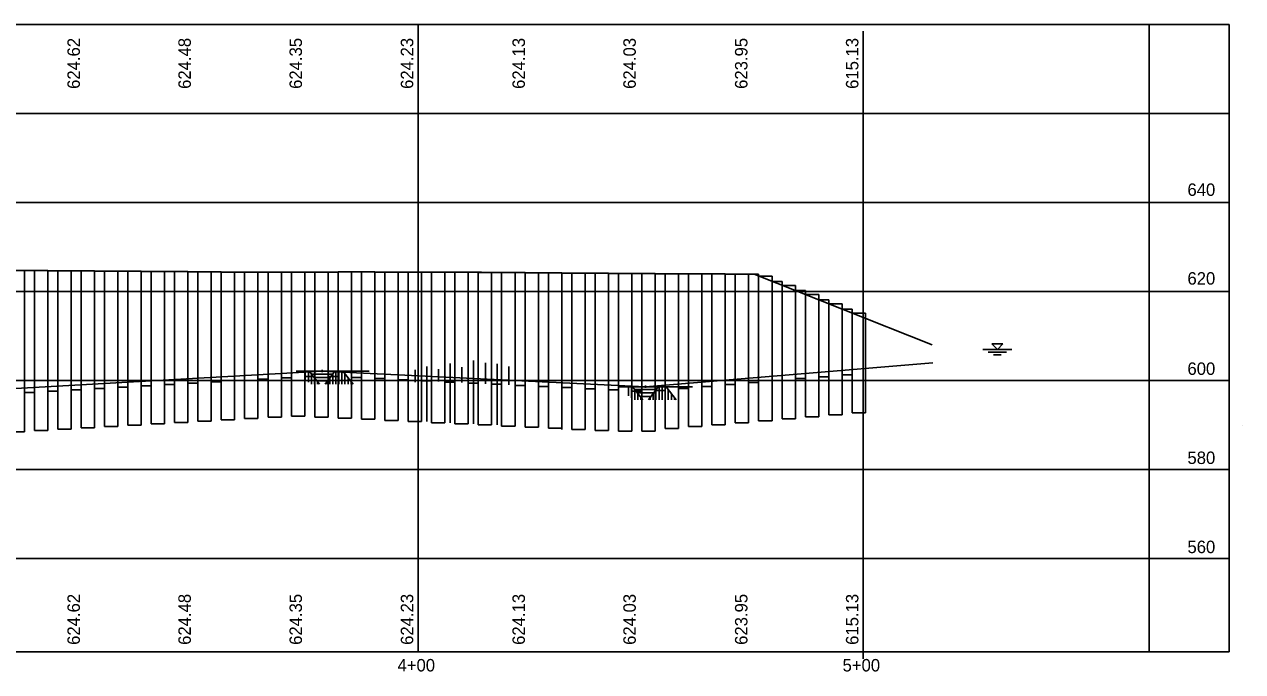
# Model space of a CAD drawing. Extents: x 2267596 to 2268160, y 712626 to 714793.
# Drawn here: x 2267886 to 2268159.8, y 713757.9 to 713903.3 of the extents above; entities that cross this region are included whole.
import ezdxf

# ---------------------------------------------------------------- set-up
doc = ezdxf.new("R2010")
doc.units = 0
for name, color, linetype in [('BR_P_Gen_Text', 7, 'Continuous'), ('BR_P_Sub_Deep_Object', 7, 'Continuous'), ('Default', 7, 'Continuous'), ('GE_X_Alignment', 7, 'Continuous'), ('PF_X_Ground_Line', 7, 'Continuous'), ('SC_Scratch1', 7, 'Continuous'), ('SC_Scratch9', 7, 'Continuous'), ('SH_Major_Grid_Line', 7, 'Continuous'), ('UT_P_Water_Cells', 7, 'Continuous'), ('XS_X_Ground_Line', 7, 'Continuous')]:
    doc.layers.add(name, color=color, linetype=linetype)

msp = doc.modelspace()

# ---------------------------------------------------------------- linework, layer by layer
at = {"layer": 'BR_P_Sub_Deep_Object'}
for p, q in [((2267883.03, 713848.02), (2267886.03, 713848.02)), ((2267886.03, 713848.02), (2267886.03, 713811.8)), ((2267886.03, 713848.01), (2267888.28, 713848.01)), ((2267888.28, 713848), (2267888.28, 713812.09)), ((2267888.28, 713847.99), (2267891.28, 713847.99)), ((2267891.28, 713847.99), (2267891.28, 713812.09)), ((2267891.28, 713847.97), (2267893.53, 713847.97)), ((2267893.53, 713847.97), (2267893.53, 713812.39)), ((2267893.53, 713847.95), (2267896.53, 713847.95)), ((2267896.53, 713847.95), (2267896.53, 713812.39)), ((2267896.53, 713847.93), (2267898.78, 713847.93)), ((2267898.78, 713847.93), (2267898.78, 713812.68)), ((2267898.78, 713847.92), (2267901.78, 713847.92)), ((2267901.78, 713847.92), (2267901.78, 713812.68)), ((2267901.78, 713847.9), (2267904.03, 713847.9)), ((2267904.03, 713847.9), (2267904.03, 713812.98)), ((2267904.03, 713847.88), (2267907.03, 713847.88)), ((2267907.03, 713847.88), (2267907.03, 713812.98)), ((2267907.03, 713847.86), (2267909.28, 713847.86)), ((2267909.28, 713847.86), (2267909.28, 713813.27)), ((2267909.28, 713847.85), (2267912.28, 713847.85)), ((2267912.28, 713847.85), (2267912.28, 713813.27)), ((2267912.28, 713847.83), (2267914.53, 713847.83)), ((2267914.53, 713847.82), (2267914.53, 713813.57)), ((2267914.53, 713847.81), (2267917.53, 713847.81)), ((2267917.53, 713847.81), (2267917.53, 713813.57)), ((2267917.53, 713847.78), (2267919.78, 713847.78)), ((2267919.78, 713847.78), (2267919.78, 713813.87)), ((2267919.78, 713847.77), (2267922.78, 713847.77)), ((2267922.78, 713847.76), (2267922.78, 713813.87)), ((2267922.78, 713847.74), (2267925.03, 713847.74)), ((2267925.03, 713847.74), (2267925.03, 713814.16)), ((2267925.03, 713847.72), (2267928.03, 713847.72)), ((2267928.03, 713847.72), (2267928.03, 713814.16)), ((2267928.03, 713847.7), (2267930.28, 713847.7)), ((2267930.28, 713847.7), (2267930.28, 713814.46)), ((2267930.28, 713847.68), (2267933.28, 713847.68)), ((2267933.28, 713847.68), (2267933.28, 713814.46)), ((2267933.28, 713847.66), (2267935.53, 713847.66)), ((2267935.53, 713847.66), (2267935.53, 713814.75)), ((2267935.53, 713847.64), (2267938.53, 713847.64)), ((2267938.53, 713847.65), (2267940.78, 713847.65)), ((2267938.53, 713847.64), (2267938.53, 713814.75)), ((2267940.78, 713847.65), (2267940.78, 713815.05)), ((2267940.78, 713847.65), (2267943.78, 713847.65)), ((2267943.78, 713847.66), (2267943.78, 713815.05)), ((2267943.78, 713847.66), (2267946.03, 713847.66)), ((2267946.03, 713847.67), (2267949.03, 713847.67)), ((2267946.03, 713847.66), (2267946.03, 713815.34)), ((2267949.03, 713847.67), (2267949.03, 713815.34)), ((2267949.03, 713847.67), (2267951.28, 713847.67)), ((2267951.28, 713847.68), (2267951.28, 713815.11)), ((2267951.28, 713847.68), (2267954.28, 713847.68)), ((2267954.28, 713847.68), (2267954.28, 713815.11)), ((2267954.28, 713847.68), (2267956.53, 713847.68)), ((2267956.53, 713847.69), (2267956.53, 713814.86)), ((2267956.53, 713847.69), (2267959.53, 713847.69)), ((2267959.53, 713847.69), (2267959.53, 713814.86)), ((2267959.53, 713847.69), (2267961.78, 713847.69)), ((2267961.78, 713847.69), (2267961.78, 713814.6)), ((2267961.78, 713847.69), (2267964.78, 713847.69)), ((2267964.78, 713847.69), (2267964.78, 713814.6)), ((2267964.78, 713847.68), (2267967.03, 713847.68)), ((2267967.03, 713847.68), (2267967.03, 713814.35)), ((2267967.03, 713847.68), (2267970.03, 713847.68)), ((2267970.03, 713847.68), (2267970.03, 713814.35)), ((2267970.03, 713847.67), (2267972.28, 713847.67)), ((2267972.28, 713847.67), (2267972.28, 713814.1)), ((2267972.28, 713847.66), (2267975.28, 713847.66)), ((2267975.28, 713847.66), (2267975.28, 713814.1)), ((2267975.28, 713847.66), (2267977.53, 713847.66)), ((2267977.53, 713847.65), (2267977.53, 713813.84)), ((2267977.53, 713847.65), (2267980.53, 713847.65)), ((2267980.53, 713847.65), (2267980.53, 713813.84)), ((2267980.53, 713847.64), (2267982.78, 713847.64)), ((2267982.78, 713847.64), (2267982.78, 713813.59)), ((2267982.78, 713847.63), (2267985.78, 713847.63)), ((2267985.78, 713847.63), (2267985.78, 713813.59)), ((2267985.78, 713847.63), (2267988.03, 713847.63)), ((2267988.03, 713847.62), (2267988.03, 713813.34)), ((2267988.03, 713847.61), (2267991.03, 713847.61)), ((2267991.03, 713847.61), (2267991.03, 713813.34)), ((2267991.03, 713847.58), (2267993.28, 713847.58)), ((2267993.28, 713847.58), (2267993.28, 713813.09)), ((2267993.28, 713847.56), (2267996.28, 713847.56)), ((2267996.28, 713847.56), (2267996.28, 713813.09)), ((2267996.28, 713847.54), (2267998.53, 713847.54)), ((2267998.53, 713847.54), (2267998.53, 713812.83)), ((2267998.53, 713847.52), (2268001.53, 713847.52)), ((2268001.53, 713847.52), (2268001.53, 713812.83)), ((2268001.53, 713847.5), (2268003.78, 713847.5)), ((2268003.78, 713847.49), (2268003.78, 713812.58)), ((2268003.78, 713847.48), (2268006.78, 713847.48)), ((2268006.78, 713847.47), (2268006.78, 713812.33)), ((2268006.78, 713847.45), (2268009.03, 713847.45)), ((2268009.03, 713847.45), (2268009.03, 713812.33)), ((2268009.03, 713847.43), (2268012.03, 713847.43)), ((2268012.03, 713847.43), (2268012.03, 713812.33)), ((2268012.03, 713847.41), (2268014.28, 713847.41)), ((2268014.28, 713847.41), (2268014.28, 713812.07)), ((2268014.28, 713847.39), (2268017.28, 713847.39)), ((2268017.28, 713847.39), (2268017.28, 713812.07)), ((2268017.28, 713847.38), (2268019.53, 713847.38)), ((2268019.53, 713847.37), (2268019.53, 713811.93)), ((2268019.53, 713847.36), (2268022.53, 713847.36)), ((2268022.53, 713847.36), (2268022.53, 713811.93)), ((2268022.53, 713847.34), (2268024.78, 713847.34)), ((2268024.78, 713847.34), (2268024.78, 713811.93)), ((2268024.78, 713847.33), (2268027.78, 713847.33)), ((2268027.78, 713847.33), (2268027.78, 713811.93)), ((2268027.78, 713847.31), (2268030.03, 713847.31)), ((2268030.03, 713847.31), (2268030.03, 713812.51)), ((2268030.03, 713847.29), (2268033.03, 713847.29)), ((2268033.03, 713847.29), (2268033.03, 713812.51)), ((2268033.03, 713847.27), (2268035.28, 713847.27)), ((2268035.28, 713847.27), (2268035.28, 713812.95)), ((2268035.28, 713847.26), (2268038.28, 713847.26)), ((2268038.28, 713847.26), (2268038.28, 713812.95)), ((2268038.28, 713847.26), (2268040.53, 713847.26)), ((2268040.53, 713847.24), (2268040.53, 713813.39)), ((2268040.53, 713847.24), (2268043.53, 713847.24)), ((2268043.53, 713847.22), (2268043.53, 713813.39)), ((2268043.53, 713847.21), (2268045.78, 713847.21)), ((2268045.78, 713847.21), (2268045.78, 713813.83)), ((2268045.78, 713847.18), (2268048.78, 713847.18)), ((2268048.78, 713847.18), (2268048.78, 713813.83)), ((2268048.78, 713847.18), (2268051.03, 713847.18)), ((2268051.03, 713847.18), (2268051.03, 713814.27)), ((2268051.03, 713846.77), (2268054.03, 713846.77)), ((2268054.03, 713846.77), (2268054.03, 713814.27)), ((2268054.03, 713845.58), (2268056.28, 713845.58)), ((2268056.28, 713845.58), (2268056.28, 713814.7)), ((2268056.28, 713844.69), (2268059.28, 713844.69)), ((2268059.28, 713844.69), (2268059.28, 713814.7)), ((2268059.28, 713843.5), (2268061.53, 713843.5)), ((2268061.53, 713843.5), (2268061.53, 713815.14)), ((2268061.53, 713842.6), (2268064.53, 713842.6)), ((2268064.53, 713842.6), (2268064.53, 713815.14)), ((2268064.53, 713841.41), (2268066.78, 713841.41)), ((2268066.78, 713841.41), (2268066.78, 713815.58)), ((2268066.78, 713840.52), (2268069.78, 713840.52)), ((2268069.78, 713840.52), (2268069.78, 713815.58)), ((2268069.78, 713839.33), (2268072.03, 713839.33)), ((2268072.03, 713839.33), (2268072.03, 713816.02)), ((2268072.03, 713838.44), (2268075.03, 713838.44)), ((2268075.03, 713838.44), (2268075.03, 713816.02)), ((2267912.28, 713822.12), (2267914.53, 713822.12)), ((2267917.53, 713822.42), (2267919.78, 713822.42)), ((2267922.78, 713822.71), (2267925.03, 713822.71)), ((2267928.03, 713823.01), (2267930.28, 713823.01)), ((2267933.28, 713823.3), (2267935.53, 713823.3)), ((2267938.53, 713823.6), (2267940.78, 713823.6)), ((2267943.78, 713823.9), (2267946.03, 713823.9)), ((2267949.03, 713824.19), (2267951.28, 713824.19)), ((2267956.53, 713824.24), (2267954.28, 713824.24)), ((2267961.78, 713823.99), (2267959.53, 713823.99)), ((2267967.03, 713823.73), (2267964.78, 713823.73)), ((2267972.28, 713823.48), (2267970.03, 713823.48)), ((2267977.53, 713823.23), (2267975.28, 713823.23)), ((2267982.78, 713822.97), (2267980.53, 713822.97)), ((2267988.03, 713822.72), (2267985.78, 713822.72)), ((2267993.28, 713822.47), (2267991.03, 713822.47)), ((2267998.53, 713822.22), (2267996.28, 713822.22)), ((2268043.53, 713822.41), (2268045.78, 713822.41)), ((2268048.78, 713822.85), (2268051.03, 713822.85)), ((2268054.03, 713823.29), (2268056.28, 713823.29)), ((2268059.28, 713823.73), (2268061.53, 713823.73)), ((2268064.53, 713824.16), (2268066.78, 713824.16)), ((2268069.78, 713824.6), (2268072.03, 713824.6)), ((2267886.03, 713820.64), (2267888.28, 713820.64)), ((2267891.28, 713820.94), (2267893.53, 713820.94)), ((2267896.53, 713821.24), (2267898.78, 713821.24)), ((2267901.78, 713821.53), (2267904.03, 713821.53)), ((2267907.03, 713821.83), (2267909.28, 713821.83)), ((2268003.78, 713821.96), (2268001.53, 713821.96)), ((2268009.03, 713821.71), (2268006.78, 713821.71)), ((2268014.28, 713821.46), (2268012.03, 713821.46)), ((2268019.53, 713821.2), (2268017.28, 713821.2)), ((2268022.53, 713820.95), (2268024.78, 713820.95)), ((2268027.78, 713821.09), (2268030.03, 713821.09)), ((2268033.03, 713821.53), (2268035.28, 713821.53)), ((2268038.28, 713821.97), (2268040.53, 713821.97)), ((2267919.78, 713813.87), (2267922.78, 713813.87)), ((2267925.03, 713814.16), (2267928.03, 713814.16)), ((2267930.28, 713814.46), (2267933.28, 713814.46)), ((2267935.53, 713814.75), (2267938.53, 713814.75)), ((2267940.78, 713815.05), (2267943.78, 713815.05)), ((2267946.03, 713815.34), (2267949.03, 713815.34)), ((2267954.28, 713815.11), (2267951.28, 713815.11)), ((2267959.53, 713814.86), (2267956.53, 713814.86)), ((2267964.78, 713814.6), (2267961.78, 713814.6)), ((2267970.03, 713814.35), (2267967.03, 713814.35)), ((2267975.28, 713814.1), (2267972.28, 713814.1)), ((2267980.53, 713813.84), (2267977.53, 713813.84)), ((2268045.78, 713813.83), (2268048.78, 713813.83)), ((2268051.03, 713814.27), (2268054.03, 713814.27)), ((2268056.28, 713814.7), (2268059.28, 713814.7)), ((2268061.53, 713815.14), (2268064.53, 713815.14)), ((2268066.78, 713815.58), (2268069.78, 713815.58)), ((2268072.03, 713816.02), (2268075.03, 713816.02)), ((2267883.03, 713811.8), (2267886.03, 713811.8)), ((2267888.28, 713812.09), (2267891.28, 713812.09)), ((2267893.53, 713812.39), (2267896.53, 713812.39)), ((2267898.78, 713812.68), (2267901.78, 713812.68)), ((2267904.03, 713812.98), (2267907.03, 713812.98)), ((2267909.28, 713813.27), (2267912.28, 713813.27)), ((2267914.53, 713813.57), (2267917.53, 713813.57)), ((2267985.78, 713813.59), (2267982.78, 713813.59)), ((2267991.03, 713813.34), (2267988.03, 713813.34)), ((2267996.28, 713813.09), (2267993.28, 713813.09)), ((2268001.53, 713812.83), (2267998.53, 713812.83)), ((2268006.78, 713812.58), (2268003.78, 713812.58)), ((2268012.03, 713812.33), (2268009.03, 713812.33)), ((2268017.28, 713812.07), (2268014.28, 713812.07)), ((2268019.53, 713811.93), (2268022.53, 713811.93)), ((2268024.78, 713811.93), (2268027.78, 713811.93)), ((2268030.03, 713812.51), (2268033.03, 713812.51)), ((2268035.28, 713812.95), (2268038.28, 713812.95)), ((2268040.53, 713813.39), (2268043.53, 713813.39))]:
    msp.add_line(p, q, dxfattribs=at)
at = {"layer": 'Default'}
for p, q in [((2267963.53, 713825.41), (2267947.14, 713825.41)), ((2267949.16, 713825.41), (2267949.16, 713823.35)), ((2267949.85, 713825.41), (2267949.85, 713822.92)), ((2267950.06, 713825.41), (2267952.34, 713822.46)), ((2267950.54, 713824.8), (2267950.54, 713822.46)), ((2267955.31, 713824.77), (2267950.54, 713824.77)), ((2267955.77, 713825.41), (2267953.64, 713822.46)), ((2267955.31, 713824.77), (2267955.31, 713822.46)), ((2267956, 713825.41), (2267956, 713822.46)), ((2267956.69, 713825.41), (2267956.69, 713822.46)), ((2267957.38, 713825.41), (2267957.38, 713822.46)), ((2267957.6, 713825.41), (2267959.88, 713822.46)), ((2267958.07, 713824.8), (2267958.07, 713822.46)), ((2267954.76, 713824.01), (2267951.14, 713824.01)), ((2267951.23, 713823.9), (2267951.23, 713822.46)), ((2267954.19, 713823.22), (2267951.75, 713823.22)), ((2267951.91, 713823.02), (2267951.91, 713822.46)), ((2267954.01, 713822.97), (2267954.01, 713822.46)), ((2267954.66, 713823.87), (2267954.66, 713822.46)), ((2267958.76, 713823.9), (2267958.76, 713822.46)), ((2267959.45, 713823.02), (2267959.45, 713822.46)), ((2268036.18, 713821.91), (2268019.79, 713821.91)), ((2268021.8, 713821.91), (2268021.8, 713819.85)), ((2268022.49, 713821.91), (2268022.49, 713819.42)), ((2268022.71, 713821.91), (2268024.99, 713818.96)), ((2268023.18, 713821.3), (2268023.18, 713818.96)), ((2268027.96, 713821.27), (2268023.18, 713821.27)), ((2268027.4, 713820.51), (2268023.79, 713820.51)), ((2268023.87, 713820.4), (2268023.87, 713818.96)), ((2268026.83, 713819.72), (2268024.4, 713819.72)), ((2268024.56, 713819.52), (2268024.56, 713818.96)), ((2268028.42, 713821.91), (2268026.28, 713818.96)), ((2268026.65, 713819.47), (2268026.65, 713818.96)), ((2268027.3, 713820.37), (2268027.3, 713818.96)), ((2268027.96, 713821.27), (2268027.96, 713818.96)), ((2268028.65, 713821.91), (2268028.65, 713818.96)), ((2268029.34, 713821.91), (2268029.34, 713818.96)), ((2268030.03, 713821.91), (2268030.03, 713818.96)), ((2268030.25, 713821.91), (2268032.52, 713818.96)), ((2268030.72, 713821.3), (2268030.72, 713818.96)), ((2268031.41, 713820.4), (2268031.41, 713818.96)), ((2268032.09, 713819.52), (2268032.09, 713818.96))]:
    msp.add_line(p, q, dxfattribs=at)
at = {"layer": 'GE_X_Alignment'}
for p, q in [((2267974.53, 713762.33), (2267974.53, 713903.31)), ((2268074.53, 713760.76), (2268074.53, 713901.75)), ((2268138.74, 713762.33), (2268138.74, 713903.31)), ((2267595.7, 713883.31), (2268156.77, 713883.31)), ((2267595.7, 713863.31), (2268156.77, 713863.31)), ((2267595.7, 713843.31), (2268156.77, 713843.31)), ((2267595.7, 713823.31), (2268156.77, 713823.31)), ((2267595.7, 713803.31), (2268156.77, 713803.31)), ((2267595.7, 713783.31), (2268156.77, 713783.31))]:
    msp.add_line(p, q, dxfattribs=at)
at = {"layer": 'PF_X_Ground_Line'}
msp.add_line((2268159.73, 713813.12), (2268159.78, 713813.12), dxfattribs=at)
at = {"layer": 'SC_Scratch1'}
for p, q in [((2267986.99, 713813.59), (2267986.99, 713827.81)), ((2267973.87, 713822.96), (2267973.87, 713825.72)), ((2267976.49, 713814.1), (2267976.49, 713826.48)), ((2267979.12, 713823.1), (2267979.12, 713825.85)), ((2267981.74, 713813.84), (2267981.74, 713827.17)), ((2267984.37, 713822.84), (2267984.37, 713826.33)), ((2267989.62, 713822.59), (2267989.62, 713827.26)), ((2267992.24, 713813.34), (2267992.24, 713827.08)), ((2267994.87, 713822.34), (2267994.87, 713826.44))]:
    msp.add_line(p, q, dxfattribs=at)
at = {"layer": 'SC_Scratch9'}
for p, q in [((2267952.95, 713825.19), (2267952.95, 713825.72)), ((2268025.6, 713821.69), (2268025.6, 713822.22))]:
    msp.add_line(p, q, dxfattribs=at)
at = {"layer": 'SH_Major_Grid_Line'}
for p, q in [((2268156.77, 713903.31), (2267595.7, 713903.31)), ((2268156.77, 713762.33), (2268156.77, 713903.31)), ((2268156.77, 713762.33), (2267595.7, 713762.33))]:
    msp.add_line(p, q, dxfattribs=at)
at = {"layer": 'UT_P_Water_Cells'}
for p, q in [((2268101.42, 713830.31), (2268107.89, 713830.31)), ((2268104.66, 713830.31), (2268103.39, 713831.58)), ((2268103.39, 713831.58), (2268105.92, 713831.58)), ((2268104.66, 713830.31), (2268105.92, 713831.58)), ((2268102.62, 713829.71), (2268106.69, 713829.71)), ((2268103.82, 713829.11), (2268105.49, 713829.11))]:
    msp.add_line(p, q, dxfattribs=at)
at = {"layer": 'XS_X_Ground_Line'}
for p, q in [((2268049.99, 713847.18), (2268090, 713831.31)), ((2268025.6, 713821.91), (2268090.2, 713827.31))]:
    msp.add_line(p, q, dxfattribs=at)
for points in [[(2267638.74, 713849.74), (2267663.74, 713849.7), (2267688.74, 713849.68), (2267713.74, 713849.46), (2267738.74, 713849.22), (2267788.74, 713848.72), (2267813.74, 713848.56), (2267838.74, 713848.39), (2267863.74, 713848.15), (2267888.74, 713848), (2267913.74, 713847.83), (2267938.74, 713847.63), (2267963.74, 713847.69), (2267988.74, 713847.62), (2268013.74, 713847.41), (2268049.99, 713847.18)], [(2267694.36, 713823.21), (2267751.31, 713826.51), (2267874.79, 713821.01), (2267952.95, 713825.41), (2268025.6, 713821.91)]]:
    msp.add_lwpolyline(points, dxfattribs=at)

# ---------------------------------------------------------------- texts
at = {"layer": 'BR_P_Gen_Text'}
for s, p in [('624.62', (2267898.51, 713888.82)), ('624.48', (2267923.44, 713888.82)), ('624.35', (2267948.41, 713888.82)), ('624.23', (2267973.42, 713888.82)), ('624.13', (2267998.51, 713888.82)), ('624.03', (2268023.42, 713888.82)), ('623.95', (2268048.51, 713888.82)), ('615.13', (2268073.44, 713888.82)), ('624.62', (2267898.51, 713763.93)), ('624.48', (2267923.44, 713763.93)), ('624.35', (2267948.41, 713763.93)), ('624.23', (2267973.42, 713763.93)), ('624.13', (2267998.51, 713763.93)), ('624.03', (2268023.42, 713763.93)), ('623.95', (2268048.51, 713763.93)), ('615.13', (2268073.44, 713763.93))]:
    msp.add_text(s, height=2.8, rotation=90, dxfattribs=at).set_placement(p)
for s, p in [('640', (2268147.38, 713864.78)), ('620', (2268147.38, 713844.85)), ('600', (2268147.38, 713824.58)), ('580', (2268147.38, 713804.56)), ('560', (2268147.38, 713784.54)), ('4+00', (2267969.88, 713757.96)), ('5+00', (2268069.88, 713757.96))]:
    msp.add_text(s, height=2.8, dxfattribs=at).set_placement(p)

doc.saveas('drawing.dxf')
